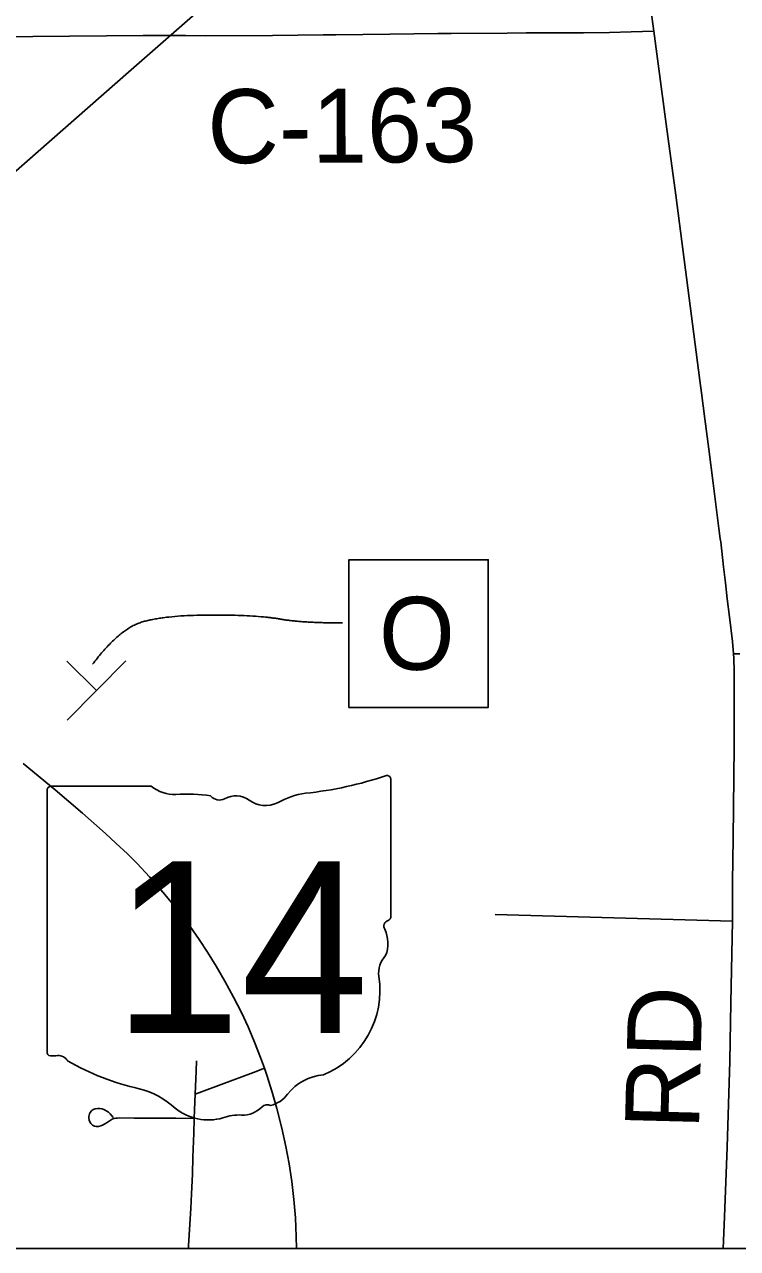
# Model space of a CAD drawing. Extents: x 0 to 34, y 0 to 22.
# Drawn here: x 5.809 to 7.177, y 4.299 to 6.648 of the extents above; entities that cross this region are included whole.
import ezdxf

# ---------------------------------------------------------------- set-up
doc = ezdxf.new("R2010")
doc.units = 0
for name, color, linetype in [('GM_X_County_Road', 7, 'Continuous'), ('GM_X_County_Road_Text', 7, 'Continuous'), ('GM_X_Rail_Line', 7, 'Continuous'), ('GM_X_State_Route', 7, 'Continuous'), ('GM_X_State_Shield', 7, 'Continuous'), ('GM_X_Township_Road', 7, 'Continuous'), ('SH_Text', 7, 'Continuous'), ('SN_P_Signs', 7, 'Continuous')]:
    doc.layers.add(name, color=color, linetype=linetype)

msp = doc.modelspace()

# ---------------------------------------------------------------- linework, layer by layer
at = {"layer": 'GM_X_County_Road'}
for p, q in [((6.2849, 6.6274), (6.3823, 6.6285)), ((6.3823, 6.6285), (6.4066, 6.6288)), ((6.7717, 6.6323), (6.7966, 6.6322)), ((7.1079, 5.9417), (7.1047, 5.9653))]:
    msp.add_line(p, q, dxfattribs=at)
for points in [[(7.0166, 6.6358), (7.0053, 6.7207), (6.9833, 6.8756), (6.9767, 6.928), (6.9696, 6.9835), (6.9614, 7.0451), (6.958, 7.0755), (6.9566, 7.0932), (6.9563, 7.1018), (6.9563, 7.1151), (6.957, 7.155), (6.9589, 7.2195), (6.9603, 7.2537), (6.9612, 7.2826), (6.9615, 7.2985), (6.962, 7.3418), (6.9618, 7.3648), (6.9612, 7.3858), (6.9604, 7.4147)], [(5.5575, 6.6231), (5.6638, 6.6243), (5.8252, 6.6251), (6.037, 6.627), (6.051, 6.627)], [(6.051, 6.627), (6.118, 6.627), (6.1563, 6.6268), (6.2849, 6.6274)], [(6.4066, 6.6288), (6.51, 6.63), (6.6018, 6.6308)], [(6.6018, 6.6308), (6.6253, 6.6309), (6.6278, 6.6309)], [(6.6278, 6.6309), (6.7349, 6.6317), (6.7717, 6.6323)], [(6.7966, 6.6322), (6.8817, 6.6321), (6.9312, 6.6331), (6.9729, 6.6341), (7.0166, 6.6358)], [(7.1047, 5.9653), (7.0585, 6.3206), (7.0404, 6.4569), (7.0166, 6.6358)], [(7.1305, 5.7683), (7.1222, 5.8334), (7.1143, 5.8915), (7.1079, 5.9417)], [(7.1693, 5.4408), (7.1673, 5.4643), (7.1619, 5.5112), (7.1575, 5.5462), (7.1539, 5.5769), (7.1504, 5.6076), (7.1448, 5.6552), (7.144, 5.6612), (7.1415, 5.681), (7.1305, 5.7683)], [(7.1673, 4.9275), (7.1676, 5.0029), (7.1685, 5.0858), (7.1705, 5.2635), (7.1706, 5.4158), (7.1703, 5.4236), (7.17, 5.432), (7.1693, 5.4408)], [(7.1693, 5.4408), (7.1815, 5.4408)], [(7.1497, 4.2991), (7.1521, 4.3599), (7.1571, 4.4935), (7.1621, 4.6588), (7.1644, 4.7704), (7.1673, 4.9275)]]:
    msp.add_lwpolyline(points, dxfattribs=at)
at = {"layer": 'GM_X_Rail_Line'}
msp.add_lwpolyline([(4.631, 5.3498), (4.7, 5.4104), (4.8512, 5.5428), (5.0065, 5.6787), (5.1355, 5.7912), (5.3567, 5.9853), (5.7346, 6.3169), (6.0085, 6.5567), (6.1878, 6.7145), (6.2934, 6.806), (6.5822, 7.0593), (6.7081, 7.1697), (6.8704, 7.3121), (7.0343, 7.4557), (7.122, 7.532), (7.1883, 7.5902)], dxfattribs=at)
at = {"layer": 'GM_X_State_Route'}
for points in [[(5.8066, 5.2303), (5.8677, 5.1793), (5.9201, 5.1349), (5.9643, 5.0957), (5.9845, 5.077), (6.0064, 5.0564), (6.0253, 5.0378), (6.0486, 5.0127), (6.0742, 4.9833), (6.094, 4.9593), (6.1103, 4.9385), (6.1266, 4.9171), (6.1442, 4.8923), (6.1604, 4.8678), (6.177, 4.8407), (6.1934, 4.8125), (6.2103, 4.7815), (6.2253, 4.7524), (6.238, 4.7248), (6.2505, 4.6954), (6.2619, 4.6657), (6.2693, 4.645)], [(6.2693, 4.645), (6.2739, 4.6319), (6.2844, 4.5993), (6.2935, 4.5679), (6.303, 4.5301), (6.3106, 4.4951), (6.3169, 4.4614), (6.3219, 4.4275), (6.3259, 4.3935), (6.3288, 4.3578), (6.3306, 4.322), (6.3311, 4.2991)]]:
    msp.add_lwpolyline(points, dxfattribs=at)
at = {"layer": 'GM_X_State_Shield'}
for p, q in [((6.5118, 4.9369), (6.5118, 5.1986)), ((5.8527, 5.1776), (5.8527, 4.6773)), ((6.0522, 5.1862), (5.8591, 5.1862)), ((6.5118, 4.937), (6.5118, 4.9369))]:
    msp.add_line(p, q, dxfattribs=at)
for centre, radius, start, end in [((6.277, 5.8683), 0.699, 275.8445, 288.9065), ((6.5045, 5.1997), 0.00734, 351.8621, 97.738), ((5.8602, 5.1787), 0.00764, 98.1301, 188.1301), ((6.0982, 5.2443), 0.0741, 231.6195, 271.1119), ((6.1227, 4.9054), 0.2659, 80.4867, 94.9883), ((6.3662, 5.0334), 0.1406, 97.3462, 120.7689), ((6.1831, 5.1813), 0.0214, 219.7921, 297.1024), ((6.2145, 5.1235), 0.0444, 54.4667, 119.1411), ((6.2718, 5.2028), 0.0534, 233.8562, 294.8282), ((6.504, 4.9359), 0.00785, 289.6038, 7.7341), ((6.5101, 4.9177), 0.0114, 107.944, 210.337), ((6.4379, 4.8846), 0.0682, 340.033, 23.6496), ((6.5381, 4.8274), 0.0496, 136.8065, 186.9296), ((6.3162, 4.7941), 0.1748, 292.3089, 8.9858), ((5.8603, 4.6762), 0.0077, 171.9584, 258.3066), ((5.8614, 4.7274), 0.0588, 267.339, 280.6039), ((5.8735, 4.6485), 0.0212, 29.7484, 93.2717), ((6.1411, 5.098), 0.5048, 240.4129, 257.1985), ((6.3899, 4.5369), 0.0958, 94.4031, 142.5768), ((5.9906, 4.4526), 0.1579, 47.1842, 75.836), ((6.2686, 4.6289), 0.0565, 282.8732, 323.2771), ((6.1615, 4.646), 0.1002, 230.7004, 286.2918), ((6.2267, 4.6085), 0.0534, 268.777, 315.5493), ((6.275, 4.5601), 0.015, 65.7517, 132.6484), ((6.2194, 4.473), 0.0824, 85.6951, 111.2099)]:
    msp.add_arc(centre, radius, start, end, dxfattribs=at)
at = {"layer": 'GM_X_Township_Road'}
msp.add_line((6.7121, 4.9402), (7.1673, 4.9275), dxfattribs=at)
for points in [[(6.1367, 4.5954), (6.1384, 4.6397), (6.139, 4.6595)], [(6.1367, 4.5954), (6.1487, 4.5998), (6.1863, 4.6138), (6.2485, 4.6372), (6.2693, 4.645)], [(6.1347, 4.5487), (6.1355, 4.5654), (6.1367, 4.5954)], [(5.979, 4.5507), (5.9767, 4.5538), (5.9734, 4.5578), (5.9703, 4.5607), (5.967, 4.5629), (5.9624, 4.5652), (5.9579, 4.567), (5.9535, 4.5678), (5.9492, 4.568), (5.9449, 4.5675), (5.9411, 4.566), (5.9376, 4.5633), (5.9351, 4.5604), (5.9337, 4.5577), (5.9328, 4.5552), (5.9323, 4.5525), (5.9323, 4.5498), (5.9329, 4.5457), (5.9342, 4.5423), (5.9361, 4.5392), (5.9392, 4.536), (5.9433, 4.5339), (5.9471, 4.5332), (5.9511, 4.5335), (5.9557, 4.5347), (5.9597, 4.5363), (5.9632, 4.5383), (5.9677, 4.541), (5.9775, 4.5473), (5.9805, 4.5485), (5.9844, 4.5494), (5.9877, 4.5496), (5.9917, 4.5497), (6.0197, 4.5492), (6.0493, 4.5493), (6.0997, 4.5491), (6.1347, 4.5487)], [(6.1311, 4.442), (6.1322, 4.4743), (6.1337, 4.5206), (6.1347, 4.5487)], [(6.1237, 4.2991), (6.124, 4.3047), (6.1279, 4.3762), (6.1292, 4.404), (6.1311, 4.442)]]:
    msp.add_lwpolyline(points, dxfattribs=at)
at = {"layer": 'SH_Text'}
for points in [[(1.6712, 21.2991), (18.6712, 21.2991), (18.6712, 4.2991), (1.6712, 4.2991)], [(6.4314, 5.3377), (6.6989, 5.3377), (6.6989, 5.6212), (6.4314, 5.6212)]]:
    msp.add_lwpolyline(points, close=True, dxfattribs=at)
msp.add_open_spline([(6.4189, 5.4998), (6.3409, 5.4998), (6.2552, 5.515), (6.0839, 5.515), (5.9918, 5.4901), (5.9398, 5.4206)], degree=2, dxfattribs=at)
at = {"layer": 'SN_P_Signs'}
for p, q in [((5.9472, 5.3699), (5.8904, 5.4261)), ((6.0035, 5.4268), (5.891, 5.313))]:
    msp.add_line(p, q, dxfattribs=at)

# ---------------------------------------------------------------- texts
at = {"layer": 'GM_X_County_Road_Text'}
for s, rotation, p in [('C-163', 0.2737, (6.1602, 6.3819)), ('RD', 88.541, (7.103, 4.5265))]:
    msp.add_text(s, height=0.14205, rotation=rotation, dxfattribs=at).set_placement(p)
at = {"layer": 'GM_X_State_Shield'}
msp.add_text('14', height=0.32959, dxfattribs=at).set_placement((5.9791, 4.7126))
at = {"layer": 'SH_Text'}
msp.add_text('O', height=0.14, dxfattribs=at).set_placement((6.4891, 5.4098))

doc.saveas('drawing.dxf')
